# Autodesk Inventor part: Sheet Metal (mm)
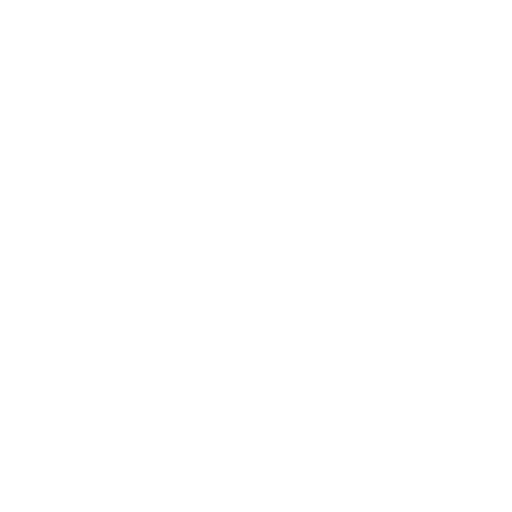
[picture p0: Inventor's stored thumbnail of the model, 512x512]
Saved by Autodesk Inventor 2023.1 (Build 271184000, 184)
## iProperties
Shininess: 64.0
Length Units: 11269
Angle Units: 11279
Time Units: 11290
Mass Units: 11283
Length Display Precision: 3
Angle Display Precision: 2
Compacted: True
Part Number: Sheet Metal (mm)
Document SubType Name: Sheet Metal
Created: 2002-07
Material: Generic
Density: 1 g/cm^3
Sheet Metal Rule: Default_mm
Appearance: Default
Density: 0.0
Volumn: 0.0
Area: 0.0
PropertySet Name: Model Information
Control State: 0
Master: False
Checked Out: False
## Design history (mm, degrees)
other parameters: "Thickness" = 0.5 (derived), "BendRadius" = 0.5 (= Thickness), "BendReliefWidth" = 0.5 (= Thickness), "BendReliefDepth" = 0.25 (= 0.5 x Thickness), "CornerReliefSize" = 2 (= 4 x Thickness), "SeamGap" = 0.01, "MinimumRemnant" = 1 (= 2 x Thickness), "TransitionRadius" = 0.5 (= BendRadius), "JacobiRadiusSize" = 0.5 (= BendRadius), "GapSize" = 0.5 (= Thickness)
